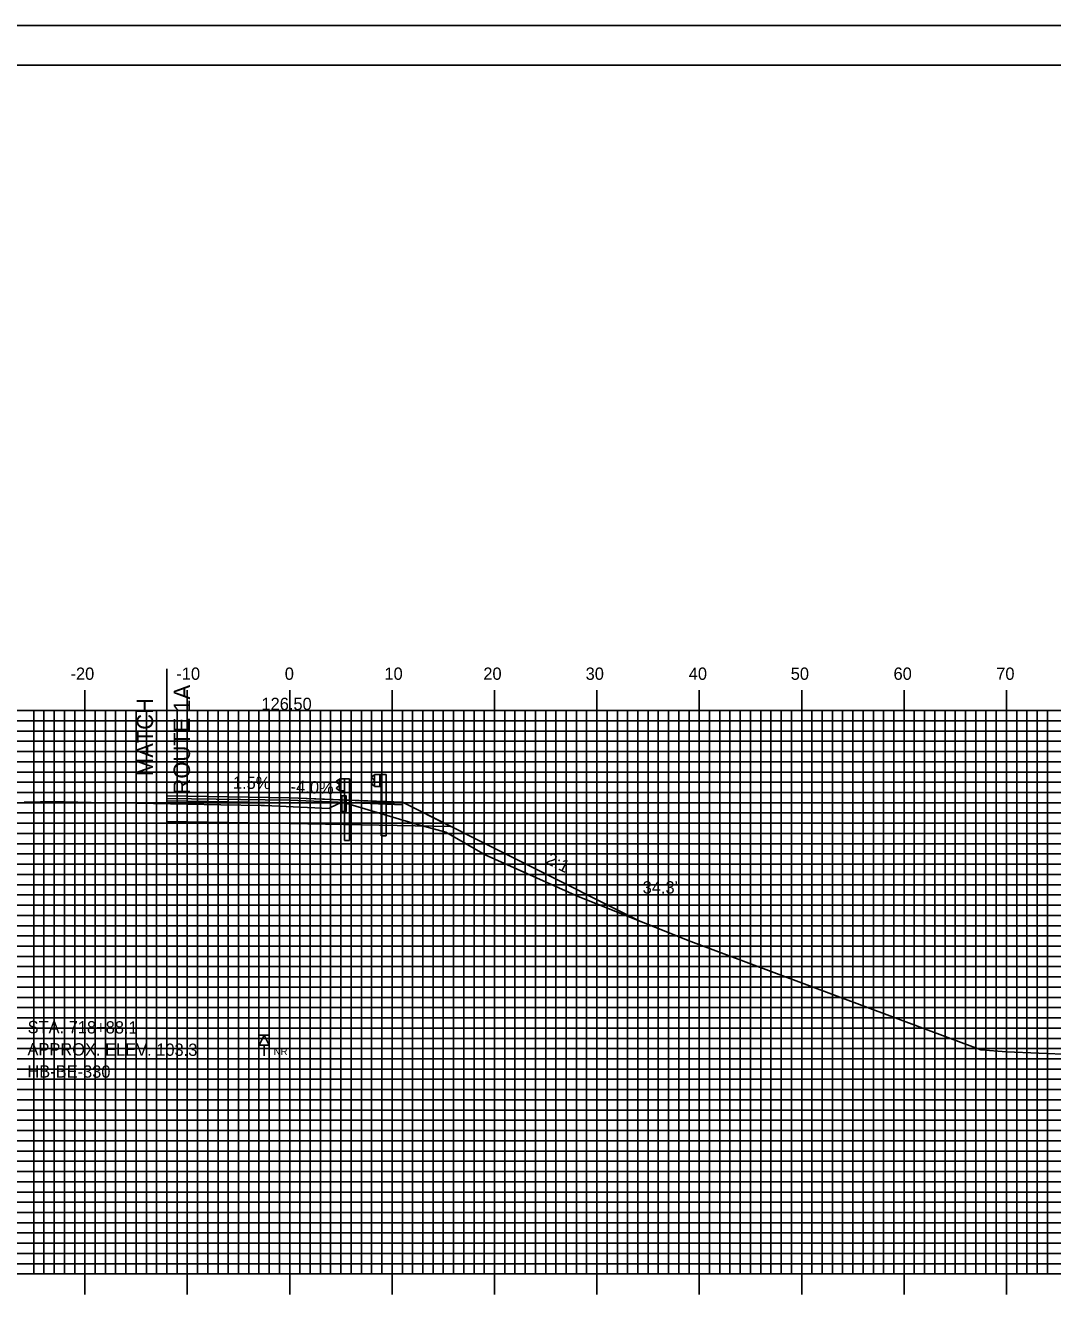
# Model space of a CAD drawing. Extents: x 857658 to 858001, y 364366 to 364586.
# Drawn here: x 857798 to 857898.3, y 364461.3 to 364585.7 of the extents above; entities that cross this region are included whole.
import ezdxf

# ---------------------------------------------------------------- set-up
doc = ezdxf.new("R2010")
doc.units = 0
for name, color, linetype in [('ANNOTATION', 7, 'Continuous'), ('BORDER', 7, 'Continuous'), ('BORING - NO REFUSAL', 7, 'Continuous'), ('D_Guardrail_Beam_Lt', 7, 'Continuous'), ('D_Roadway_Centerline', 7, 'Continuous'), ('D_Roadway_Centerline_Text', 7, 'Continuous'), ('D_Roadway_Edge_Shoulder', 7, 'Continuous'), ('D_Roadway_Edge_TW', 7, 'Continuous'), ('D_Roadway_Pavement', 7, 'Continuous'), ('D_Roadway_SlopeLines', 7, 'Continuous'), ('D_Roadway_SubGrade', 7, 'Continuous'), ('D_Text_Standard', 7, 'Continuous'), ('H_V ANNOTATION', 7, 'Continuous'), ('M_Roadway_Centerline', 7, 'Continuous'), ('MAJOR', 7, 'Continuous'), ('MINOR', 7, 'Continuous'), ('PLOT BOUNDARY', 7, 'Continuous'), ('S_Curb_Type_1', 7, 'Continuous'), ('S_Guardrail_Beam', 7, 'Continuous'), ('S_Roadway_Centerline', 7, 'Continuous')]:
    doc.layers.add(name, color=color, linetype=linetype)

msp = doc.modelspace()

# ---------------------------------------------------------------- linework, layer by layer
at = {"layer": 'BORDER'}
msp.add_lwpolyline([(857674.25, 364371.79), (857994.25, 364371.79), (857994.25, 364581.79), (857674.25, 364581.79)], close=True, dxfattribs=at)
at = {"layer": 'BORING - NO REFUSAL'}
for p, q in [((857821.83, 364487.09), (857820.87, 364487.09)), ((857821.35, 364486.13), (857821.35, 364485.07))]:
    msp.add_line(p, q, dxfattribs=at)
msp.add_lwpolyline([(857821.35, 364487.09), (857821.83, 364486.13), (857820.87, 364486.13)], close=True, dxfattribs=at)
at = {"layer": 'D_Guardrail_Beam_Lt'}
for p, q in [((857832.03, 364512.44), (857831.89, 364512.34)), ((857831.89, 364512.2), (857832.08, 364512.06)), ((857832.08, 364511.86), (857831.89, 364511.73)), ((857831.89, 364511.58), (857832.03, 364511.48)), ((857832.12, 364512.46), (857832.05, 364512.45)), ((857832.05, 364511.48), (857832.12, 364511.46)), ((857832.11, 364512), (857832.11, 364511.93)), ((857832.12, 364512.55), (857832.81, 364512.55)), ((857832.12, 364511.38), (857832.12, 364512.55)), ((857832.81, 364511.38), (857832.12, 364511.38)), ((857832.64, 364512.55), (857832.64, 364511.38)), ((857832.74, 364512.55), (857832.74, 364511.38)), ((857832.79, 364506.55), (857832.79, 364511.38)), ((857832.81, 364512.55), (857833.28, 364512.55)), ((857832.81, 364512.55), (857832.81, 364511.38)), ((857833.28, 364512.55), (857833.28, 364506.55)), ((857832.79, 364506.55), (857833.28, 364506.55))]:
    msp.add_line(p, q, dxfattribs=at)
for centre, major_axis, start_param, end_param in [((857831.94, 364512.27), (-0.0877, 0), 5.323254, 7.243116), ((857831.94, 364511.66), (-0.0877, 0), 5.323254, 7.243116), ((857832.05, 364512.41), (-0.0417, 0), 4.907132, 5.323254), ((857832.05, 364511.52), (-0.0417, 0), 0.959931, 1.376053), ((857832.04, 364512), (0.0789, 0), 0, 0.959931), ((857832.04, 364511.93), (0.0789, 0), 5.323254, 6.283185)]:
    msp.add_ellipse(centre, major_axis=major_axis, ratio=0.995501, start_param=start_param, end_param=end_param, dxfattribs=at)
at = {"layer": 'D_Roadway_Centerline'}
for p, q in [((857823.85, 364510.28), (857811.85, 364510.46)), ((857823.85, 364510.03), (857811.85, 364510.21)), ((857823.85, 364509.79), (857811.85, 364509.97)), ((857823.85, 364507.78), (857811.85, 364507.96))]:
    msp.add_line(p, q, dxfattribs=at)
at = {"layer": 'D_Roadway_Edge_Shoulder'}
for points in [[(857823.85, 364510.28), (857834.85, 364509.84), (857834.85, 364509.59), (857823.85, 364510.03)], [(857823.85, 364510.28), (857831.85, 364509.96), (857831.85, 364509.96), (857834.85, 364509.84), (857834.85, 364509.59), (857823.85, 364510.03)]]:
    msp.add_lwpolyline(points, close=True, dxfattribs=at)
at = {"layer": 'D_Roadway_Edge_TW'}
msp.add_line((857811.85, 364510.41), (857811.85, 364510.16), dxfattribs=at)
at = {"layer": 'D_Roadway_Pavement'}
msp.add_line((857811.85, 364510.16), (857811.85, 364509.91), dxfattribs=at)
msp.add_lwpolyline([(857823.85, 364510.03), (857823.85, 364509.78)], dxfattribs=at)
msp.add_lwpolyline([(857823.85, 364510.03), (857823.85, 364509.78)], dxfattribs=at)
msp.add_lwpolyline([(857823.85, 364510.03), (857823.85, 364509.78)], dxfattribs=at)
msp.add_lwpolyline([(857823.85, 364510.03), (857823.85, 364509.78)], dxfattribs=at)
at = {"layer": 'D_Roadway_SlopeLines'}
msp.add_lwpolyline([(857834.85, 364509.84), (857858.11, 364498.21)], dxfattribs=at)
at = {"layer": 'D_Roadway_SubGrade'}
for p in [(857811.85, 364522.86), (857811.85, 364509.91)]:
    msp.add_line(p, (857811.85, 364507.96), dxfattribs=at)
msp.add_lwpolyline([(857823.85, 364509.78), (857823.85, 364510.03), (857834.85, 364509.59), (857834.85, 364509.84), (857839.6, 364507.47), (857823.85, 364507.78)], close=True, dxfattribs=at)
at = {"layer": 'MAJOR'}
for p, q in [((857803.85, 364520.79), (857803.85, 364518.79)), ((857813.85, 364520.79), (857813.85, 364518.79)), ((857823.85, 364520.79), (857823.85, 364518.79)), ((857833.85, 364520.79), (857833.85, 364518.79)), ((857843.85, 364520.79), (857843.85, 364518.79)), ((857853.85, 364520.79), (857853.85, 364518.79)), ((857863.85, 364520.79), (857863.85, 364518.79)), ((857873.85, 364520.79), (857873.85, 364518.79)), ((857883.85, 364520.79), (857883.85, 364518.79)), ((857893.85, 364520.79), (857893.85, 364518.79)), ((857683.85, 364518.79), (857963.85, 364518.79)), ((857683.85, 364518.79), (857963.85, 364518.79)), ((857803.85, 364463.79), (857803.85, 364518.79)), ((857813.85, 364463.79), (857813.85, 364518.79)), ((857823.85, 364463.79), (857823.85, 364518.79)), ((857833.85, 364463.79), (857833.85, 364518.79)), ((857843.85, 364463.79), (857843.85, 364518.79)), ((857853.85, 364463.79), (857853.85, 364518.79)), ((857863.85, 364463.79), (857863.85, 364518.79)), ((857873.85, 364463.79), (857873.85, 364518.79)), ((857883.85, 364463.79), (857883.85, 364518.79)), ((857893.85, 364463.79), (857893.85, 364518.79)), ((857683.85, 364513.79), (857963.85, 364513.79)), ((857683.85, 364508.79), (857963.85, 364508.79)), ((857683.85, 364503.79), (857963.85, 364503.79)), ((857683.85, 364498.79), (857963.85, 364498.79)), ((857683.85, 364493.79), (857963.85, 364493.79)), ((857683.85, 364488.79), (857963.85, 364488.79)), ((857683.85, 364483.79), (857963.85, 364483.79)), ((857683.85, 364478.79), (857963.85, 364478.79)), ((857683.85, 364473.79), (857963.85, 364473.79)), ((857683.85, 364468.79), (857963.85, 364468.79)), ((857683.85, 364463.79), (857963.85, 364463.79)), ((857683.85, 364463.79), (857963.85, 364463.79)), ((857803.85, 364461.78), (857803.85, 364463.79)), ((857813.85, 364461.78), (857813.85, 364463.79)), ((857823.85, 364461.78), (857823.85, 364463.79)), ((857833.85, 364461.78), (857833.85, 364463.79)), ((857843.85, 364461.78), (857843.85, 364463.79)), ((857853.85, 364461.78), (857853.85, 364463.79)), ((857863.85, 364461.78), (857863.85, 364463.79)), ((857873.85, 364461.78), (857873.85, 364463.79)), ((857883.85, 364461.78), (857883.85, 364463.79)), ((857893.85, 364461.78), (857893.85, 364463.79))]:
    msp.add_line(p, q, dxfattribs=at)
at = {"layer": 'MINOR'}
for p, q in [((857683.85, 364517.79), (857963.85, 364517.79)), ((857798.85, 364463.79), (857798.85, 364518.79)), ((857799.85, 364463.79), (857799.85, 364518.79)), ((857800.85, 364463.79), (857800.85, 364518.79)), ((857801.85, 364463.79), (857801.85, 364518.79)), ((857802.85, 364463.79), (857802.85, 364518.79)), ((857804.85, 364463.79), (857804.85, 364518.79)), ((857805.85, 364463.79), (857805.85, 364518.79)), ((857806.85, 364463.79), (857806.85, 364518.79)), ((857807.85, 364463.79), (857807.85, 364518.79)), ((857808.85, 364463.79), (857808.85, 364518.79)), ((857809.85, 364463.79), (857809.85, 364518.79)), ((857810.85, 364463.79), (857810.85, 364518.79)), ((857811.85, 364463.79), (857811.85, 364518.79)), ((857812.85, 364463.79), (857812.85, 364518.79)), ((857814.85, 364463.79), (857814.85, 364518.79)), ((857815.85, 364463.79), (857815.85, 364518.79)), ((857816.85, 364463.79), (857816.85, 364518.79)), ((857817.85, 364463.79), (857817.85, 364518.79)), ((857818.85, 364463.79), (857818.85, 364518.79)), ((857819.85, 364463.79), (857819.85, 364518.79)), ((857820.85, 364463.79), (857820.85, 364518.79)), ((857821.85, 364463.79), (857821.85, 364518.79)), ((857822.85, 364463.79), (857822.85, 364518.79)), ((857824.85, 364463.79), (857824.85, 364518.79)), ((857825.85, 364463.79), (857825.85, 364518.79)), ((857826.85, 364463.79), (857826.85, 364518.79)), ((857827.85, 364463.79), (857827.85, 364518.79)), ((857828.85, 364463.79), (857828.85, 364518.79)), ((857829.85, 364463.79), (857829.85, 364518.79)), ((857830.85, 364463.79), (857830.85, 364518.79)), ((857831.85, 364463.79), (857831.85, 364518.79)), ((857832.85, 364463.79), (857832.85, 364518.79)), ((857834.85, 364463.79), (857834.85, 364518.79)), ((857835.85, 364463.79), (857835.85, 364518.79)), ((857836.85, 364463.79), (857836.85, 364518.79)), ((857837.85, 364463.79), (857837.85, 364518.79)), ((857838.85, 364463.79), (857838.85, 364518.79)), ((857839.85, 364463.79), (857839.85, 364518.79)), ((857840.85, 364463.79), (857840.85, 364518.79)), ((857841.85, 364463.79), (857841.85, 364518.79)), ((857842.85, 364463.79), (857842.85, 364518.79)), ((857844.85, 364463.79), (857844.85, 364518.79)), ((857845.85, 364463.79), (857845.85, 364518.79)), ((857846.85, 364463.79), (857846.85, 364518.79)), ((857847.85, 364463.79), (857847.85, 364518.79)), ((857848.85, 364463.79), (857848.85, 364518.79)), ((857849.85, 364463.79), (857849.85, 364518.79)), ((857850.85, 364463.79), (857850.85, 364518.79)), ((857851.85, 364463.79), (857851.85, 364518.79)), ((857852.85, 364463.79), (857852.85, 364518.79)), ((857854.85, 364463.79), (857854.85, 364518.79)), ((857855.85, 364463.79), (857855.85, 364518.79)), ((857856.85, 364463.79), (857856.85, 364518.79)), ((857857.85, 364463.79), (857857.85, 364518.79)), ((857858.85, 364463.79), (857858.85, 364518.79)), ((857859.85, 364463.79), (857859.85, 364518.79)), ((857860.85, 364463.79), (857860.85, 364518.79)), ((857861.85, 364463.79), (857861.85, 364518.79)), ((857862.85, 364463.79), (857862.85, 364518.79)), ((857864.85, 364463.79), (857864.85, 364518.79)), ((857865.85, 364463.79), (857865.85, 364518.79)), ((857866.85, 364463.79), (857866.85, 364518.79)), ((857867.85, 364463.79), (857867.85, 364518.79)), ((857868.85, 364463.79), (857868.85, 364518.79)), ((857869.85, 364463.79), (857869.85, 364518.79)), ((857870.85, 364463.79), (857870.85, 364518.79)), ((857871.85, 364463.79), (857871.85, 364518.79)), ((857872.85, 364463.79), (857872.85, 364518.79)), ((857874.85, 364463.79), (857874.85, 364518.79)), ((857875.85, 364463.79), (857875.85, 364518.79)), ((857876.85, 364463.79), (857876.85, 364518.79)), ((857877.85, 364463.79), (857877.85, 364518.79)), ((857878.85, 364463.79), (857878.85, 364518.79)), ((857879.85, 364463.79), (857879.85, 364518.79)), ((857880.85, 364463.79), (857880.85, 364518.79)), ((857881.85, 364463.79), (857881.85, 364518.79)), ((857882.85, 364463.79), (857882.85, 364518.79)), ((857884.85, 364463.79), (857884.85, 364518.79)), ((857885.85, 364463.79), (857885.85, 364518.79)), ((857886.85, 364463.79), (857886.85, 364518.79)), ((857887.85, 364463.79), (857887.85, 364518.79)), ((857888.85, 364463.79), (857888.85, 364518.79)), ((857889.85, 364463.79), (857889.85, 364518.79)), ((857890.85, 364463.79), (857890.85, 364518.79)), ((857891.85, 364463.79), (857891.85, 364518.79)), ((857892.85, 364463.79), (857892.85, 364518.79)), ((857894.85, 364463.79), (857894.85, 364518.79)), ((857895.85, 364463.79), (857895.85, 364518.79)), ((857896.85, 364463.79), (857896.85, 364518.79)), ((857897.85, 364463.79), (857897.85, 364518.79)), ((857683.85, 364516.79), (857963.85, 364516.79)), ((857683.85, 364515.79), (857963.85, 364515.79)), ((857683.85, 364514.79), (857963.85, 364514.79)), ((857683.85, 364512.79), (857963.85, 364512.79)), ((857683.85, 364511.79), (857963.85, 364511.79)), ((857683.85, 364510.79), (857963.85, 364510.79)), ((857683.85, 364509.79), (857963.85, 364509.79)), ((857683.85, 364507.79), (857963.85, 364507.79)), ((857683.85, 364506.79), (857963.85, 364506.79)), ((857683.85, 364505.79), (857963.85, 364505.79)), ((857683.85, 364504.79), (857963.85, 364504.79)), ((857683.85, 364502.79), (857963.85, 364502.79)), ((857683.85, 364501.79), (857963.85, 364501.79)), ((857683.85, 364500.79), (857963.85, 364500.79)), ((857683.85, 364499.79), (857963.85, 364499.79)), ((857683.85, 364497.79), (857963.85, 364497.79)), ((857683.85, 364496.79), (857963.85, 364496.79)), ((857683.85, 364495.79), (857963.85, 364495.79)), ((857683.85, 364494.79), (857963.85, 364494.79)), ((857683.85, 364492.79), (857963.85, 364492.79)), ((857683.85, 364491.79), (857963.85, 364491.79)), ((857683.85, 364490.79), (857963.85, 364490.79)), ((857683.85, 364489.79), (857963.85, 364489.79)), ((857683.85, 364487.79), (857963.85, 364487.79)), ((857683.85, 364486.79), (857963.85, 364486.79)), ((857683.85, 364485.79), (857963.85, 364485.79)), ((857683.85, 364484.79), (857963.85, 364484.79)), ((857683.85, 364482.79), (857963.85, 364482.79)), ((857683.85, 364481.79), (857963.85, 364481.79)), ((857683.85, 364480.79), (857963.85, 364480.79)), ((857683.85, 364479.79), (857963.85, 364479.79)), ((857683.85, 364477.79), (857963.85, 364477.79)), ((857683.85, 364476.79), (857963.85, 364476.79)), ((857683.85, 364475.79), (857963.85, 364475.79)), ((857683.85, 364474.79), (857963.85, 364474.79)), ((857683.85, 364472.79), (857963.85, 364472.79)), ((857683.85, 364471.79), (857963.85, 364471.79)), ((857683.85, 364470.79), (857963.85, 364470.79)), ((857683.85, 364469.79), (857963.85, 364469.79)), ((857683.85, 364467.79), (857963.85, 364467.79)), ((857683.85, 364466.79), (857963.85, 364466.79)), ((857683.85, 364465.79), (857963.85, 364465.79)), ((857683.85, 364464.79), (857963.85, 364464.79))]:
    msp.add_line(p, q, dxfattribs=at)
at = {"layer": 'PLOT BOUNDARY'}
msp.add_lwpolyline([(857658.06, 364365.67), (857998.06, 364365.67), (857998.06, 364585.67), (857658.06, 364585.67)], close=True, dxfattribs=at)
at = {"layer": 'S_Curb_Type_1'}
msp.add_lwpolyline([(857828.95, 364510.45), (857829.37, 364510.45), (857829.37, 364508.95), (857828.95, 364508.95)], close=True, dxfattribs=at)
msp.add_lwpolyline([(857828.95, 364510.45), (857829.37, 364510.45), (857829.37, 364508.95), (857828.95, 364508.95)], close=True, dxfattribs=at)
at = {"layer": 'S_Guardrail_Beam'}
for p, q in [((857828.61, 364512.02), (857828.46, 364511.92)), ((857828.61, 364512.02), (857828.46, 364511.92)), ((857828.46, 364511.78), (857828.66, 364511.64)), ((857828.46, 364511.78), (857828.66, 364511.64)), ((857828.66, 364511.42), (857828.46, 364511.28)), ((857828.66, 364511.42), (857828.46, 364511.28)), ((857828.7, 364512.04), (857828.62, 364512.03)), ((857828.7, 364512.04), (857828.62, 364512.03)), ((857828.69, 364511.57), (857828.69, 364511.48)), ((857828.69, 364511.57), (857828.69, 364511.48)), ((857828.7, 364512.11), (857829.19, 364512.11)), ((857828.7, 364510.95), (857828.7, 364512.11)), ((857828.7, 364512.11), (857829.19, 364512.11)), ((857828.7, 364510.95), (857828.7, 364512.11)), ((857829.19, 364512.11), (857829.69, 364512.11)), ((857829.19, 364512.11), (857829.19, 364510.95)), ((857829.19, 364512.11), (857829.69, 364512.11)), ((857829.19, 364512.11), (857829.19, 364510.95)), ((857829.69, 364512.11), (857829.69, 364506.11)), ((857829.69, 364512.11), (857829.69, 364506.11)), ((857828.46, 364511.14), (857828.61, 364511.04)), ((857828.46, 364511.14), (857828.61, 364511.04)), ((857828.62, 364511.03), (857828.7, 364511.02)), ((857828.62, 364511.03), (857828.7, 364511.02)), ((857829.19, 364510.95), (857828.7, 364510.95)), ((857829.19, 364510.95), (857828.7, 364510.95)), ((857829.19, 364506.11), (857829.19, 364510.95)), ((857829.19, 364506.11), (857829.19, 364510.95)), ((857829.19, 364506.11), (857829.69, 364506.11)), ((857829.19, 364506.11), (857829.69, 364506.11))]:
    msp.add_line(p, q, dxfattribs=at)
for centre, major_axis, start_param, end_param in [((857828.51, 364511.85), (-0.0877, 0), 5.323254, 7.243116), ((857828.51, 364511.85), (-0.0877, 0), 5.323254, 7.243116), ((857828.63, 364511.98), (-0.0417, 0), 4.886922, 5.323254), ((857828.63, 364511.98), (-0.0417, 0), 4.886922, 5.323254), ((857828.61, 364511.57), (0.0789, 0), 0, 0.959931), ((857828.61, 364511.57), (0.0789, 0), 0, 0.959931), ((857828.61, 364511.48), (0.0789, 0), 5.323254, 6.283185), ((857828.61, 364511.48), (0.0789, 0), 5.323254, 6.283185), ((857828.51, 364511.21), (-0.0877, 0), 5.323254, 7.243116), ((857828.51, 364511.21), (-0.0877, 0), 5.323254, 7.243116), ((857828.63, 364511.07), (-0.0417, 0), 0.959931, 1.396263), ((857828.63, 364511.07), (-0.0417, 0), 0.959931, 1.396263)]:
    msp.add_ellipse(centre, major_axis=major_axis, ratio=0.995501, start_param=start_param, end_param=end_param, dxfattribs=at)
at = {"layer": 'S_Roadway_Centerline'}
msp.add_lwpolyline([(857797.93, 364509.86), (857799.51, 364509.88), (857800.23, 364509.89), (857801.85, 364509.87), (857804.45, 364509.83), (857807.26, 364509.79), (857817.14, 364509.6), (857821.05, 364509.52), (857821.39, 364509.51), (857827.71, 364509.24), (857827.76, 364509.29), (857828.95, 364509.86), (857829.87, 364509.59), (857829.98, 364509.56), (857835.79, 364507.83), (857836.57, 364507.59), (857839.11, 364506.92), (857842.94, 364504.69), (857852.02, 364500.64), (857863.01, 364496.26), (857891.34, 364485.67), (857893.86, 364485.46), (857903.34, 364485.07)], dxfattribs=at)

# ---------------------------------------------------------------- texts
at = {"layer": 'ANNOTATION'}
for s, height, rotation, p in [('ROUTE 1A', 1.6, 90, (857814.11, 364510.6)), ('MATCH', 1.6, 90, (857810.51, 364512.4)), ('1.5%', 1.2, 359.4146, (857818.3, 364511.16)), ('-4.0%', 1.2, 357.7094, (857823.93, 364510.79)), ('2:1', 1.2, 333.4349, (857848.79, 364503.91))]:
    msp.add_text(s, height=height, rotation=rotation, dxfattribs=at).set_placement(p)
at = {"layer": 'BORING - NO REFUSAL'}
for s, p in [('STA. 718+88.1', (857798.25, 364487.29)), ('APPROX. ELEV. 103.3', (857798.24, 364485.13)), ('HB-BE-330', (857798.23, 364482.97))]:
    msp.add_text(s, height=1.2, rotation=359.8142, dxfattribs=at).set_placement(p)
msp.add_text('NR', height=0.7, dxfattribs=at).set_placement((857822.28, 364485.17))
at = {"layer": 'D_Roadway_Centerline_Text'}
msp.add_text('126.50', height=1.2, dxfattribs=at).set_placement((857821.09, 364518.84))
at = {"layer": 'D_Text_Standard'}
msp.add_text("34.3'", height=1.2, dxfattribs=at).set_placement((857858.32, 364500.93))
at = {"layer": 'H_V ANNOTATION'}
for s, p in [('-20', (857802.44, 364521.79)), ('-10', (857812.78, 364521.79)), ('0', (857823.37, 364521.79)), ('10', (857833.1, 364521.79)), ('20', (857842.76, 364521.79)), ('30', (857852.75, 364521.79)), ('40', (857862.82, 364521.79)), ('50', (857872.78, 364521.79)), ('60', (857882.82, 364521.79)), ('70', (857892.85, 364521.79))]:
    msp.add_text(s, height=1.2, dxfattribs=at).set_placement(p)
at = {"layer": 'M_Roadway_Centerline'}
for s, p in [('C', (857800.23, 364509.89)), ('L', (857800.23, 364509.88))]:
    msp.add_text(s, height=0.0146, dxfattribs=at).set_placement(p)

doc.saveas('drawing.dxf')
